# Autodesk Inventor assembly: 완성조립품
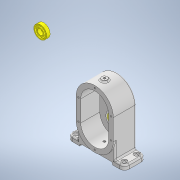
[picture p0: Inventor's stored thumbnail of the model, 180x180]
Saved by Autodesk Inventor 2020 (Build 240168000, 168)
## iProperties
Created: 2021-05
Part Number: 완성조립품
Document SubType Name: Assembly
Designer: Owner
Author: Owner
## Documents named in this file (4)
- C:\Users\Owner\Desktop\710507V1013\완성조립품.iam
- C:\Users\Owner\Desktop\710507V1013\1-본체.ipt
- C:\Users\Owner\Desktop\710507V1013\베어링 6001.ipt
- 베어링 6001.ipt
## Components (1 placed, 1 different names)
1. 1-본체:1
